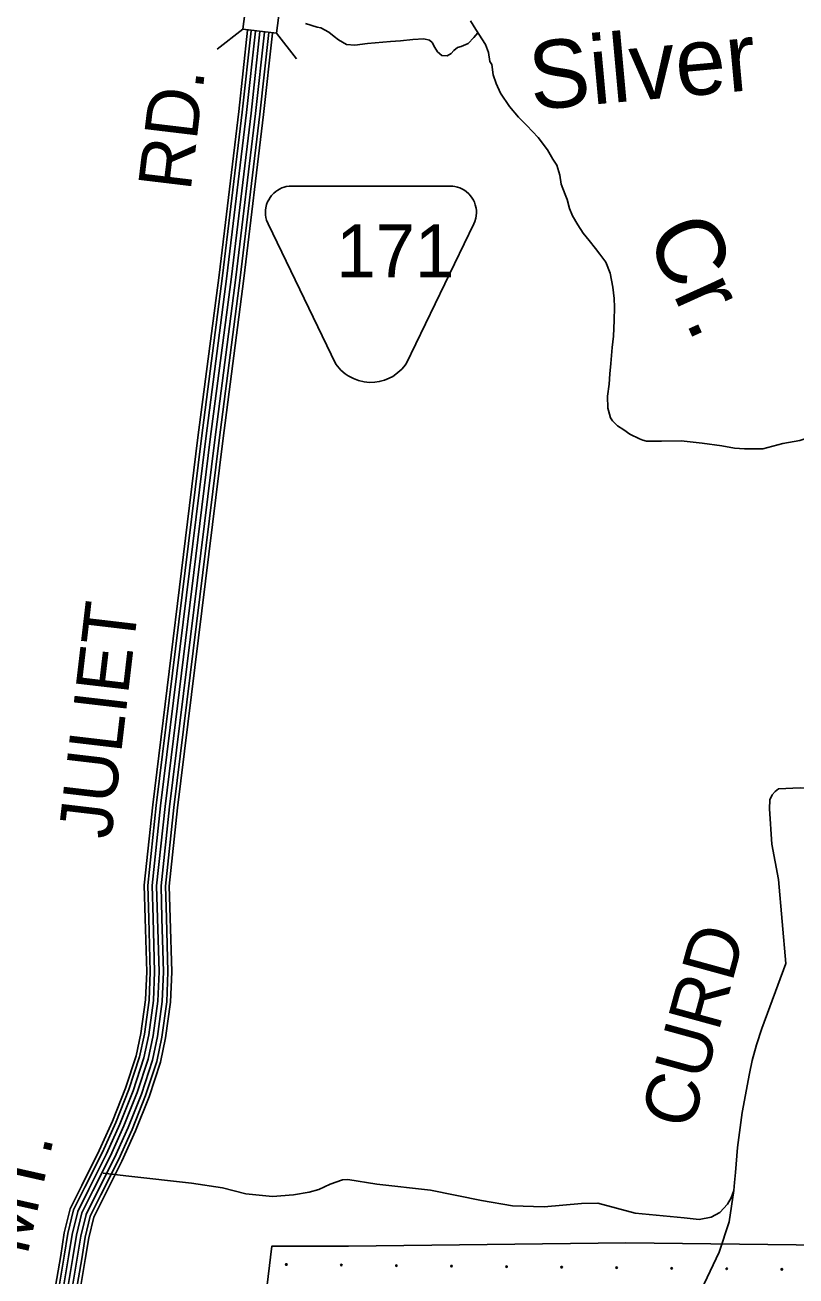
# Model space of a CAD drawing. Extents: x 1788175 to 1969470, y 584502 to 738744.
# Drawn here: x 1815246 to 1820631, y 681239 to 689981 of the extents above; entities that cross this region are included whole.
import ezdxf

# ---------------------------------------------------------------- set-up
doc = ezdxf.new("R2010")
doc.units = 0
for name, color, linetype in [('DESIGN - DRAINAGE - Bridges and Cross Drains Size Text', 7, 'Continuous'), ('DESIGN - EROSION CONTROL - Devices', 7, 'Continuous'), ('DESIGN - ROW - Easement Linework and Patterning', 7, 'Continuous'), ('DESIGN - ROW - Right-of-Way and Easement Labels', 7, 'Continuous'), ('DESIGN - SCRATCH - User 1', 7, 'Continuous'), ('DESIGN - TRANSPORTATION - Text', 7, 'Continuous'), ('SURVEY - CONTOURS - Intermediate with optional Text', 7, 'Continuous'), ('SURVEY - CONTROL with Text', 7, 'Continuous'), ('SURVEY - DRAINAGE - Area Shapes', 7, 'Continuous'), ('SURVEY - DRAINAGE - Storm Sewer', 7, 'Continuous')]:
    doc.layers.add(name, color=color, linetype=linetype)

msp = doc.modelspace()

# ---------------------------------------------------------------- linework, layer by layer
at = {"layer": 'DESIGN - EROSION CONTROL - Devices'}
for centre in [(1817071.7, 681319.3), (1817456.2, 681315.5), (1817840.8, 681311.8), (1818225.3, 681308.1), (1818609.9, 681304.3), (1818994.4, 681300.6), (1819379, 681296.9), (1819763.5, 681293.1), (1820148.1, 681289.4), (1820532.6, 681285.7)]:
    msp.add_circle(centre, 5.28, dxfattribs=at)
at = {"layer": 'DESIGN - ROW - Easement Linework and Patterning'}
for points in [[(1817418.4, 687609.8), (1816943.9, 688590.3), (1816933.4, 688617.3), (1816928.9, 688635.3), (1816926.3, 688653.2), (1816925.5, 688668.8), (1816926.2, 688686.6), (1816928.3, 688703.1), (1816934, 688726.3), (1816940.6, 688743.9), (1816948.5, 688760), (1816958.5, 688776.2), (1816968.8, 688789.7), (1816984.2, 688805.9), (1816998.5, 688817.9), (1817011.7, 688827.1), (1817024.4, 688834.4), (1817040.9, 688842.1), (1817056.6, 688847.6), (1817069.3, 688851), (1817091, 688854.6), (1817110.3, 688855.6)], [(1818381, 688590.3), (1818387.1, 688608), (1818395.1, 688631.1), (1818398, 688647.8), (1818399.4, 688668.2), (1818399, 688683.4), (1818396.9, 688701.4), (1818391.7, 688723.8), (1818385.1, 688742), (1818378.3, 688756.5), (1818369.7, 688771.4), (1818358, 688787.4), (1818345.4, 688801.3), (1818326.7, 688817.7), (1818311.8, 688827.9), (1818297.9, 688835.7), (1818283.6, 688842.2), (1818267.4, 688847.9), (1818247.6, 688852.6), (1818233.7, 688854.6), (1818214.6, 688855.6), (1817110.3, 688855.6)], [(1818381, 688590.3), (1817907.9, 687612.7), (1817892.7, 687592.4), (1817878.3, 687576.1), (1817865, 687563), (1817836.9, 687539.9), (1817814.8, 687525.3), (1817790.8, 687512.5), (1817758, 687499.1), (1817720.3, 687489), (1817688.6, 687484.5), (1817653.6, 687483.4), (1817616.2, 687486.8), (1817575.8, 687496.1), (1817540, 687509.5), (1817504.4, 687528.5), (1817482.4, 687543.5), (1817453, 687569), (1817418.4, 687609.8)]]:
    msp.add_lwpolyline(points, dxfattribs=at)
at = {"layer": 'DESIGN - SCRATCH - User 1'}
msp.add_line((1819442.8, 681470.8), (1821367.4, 681447.5), dxfattribs=at)
msp.add_lwpolyline([(1816364.3, 676041.4), (1816697.1, 679318.3), (1816771.7, 679848.1), (1816876.6, 680677), (1816969.9, 681447.5), (1817506.5, 681447.5), (1819442.8, 681470.8)], dxfattribs=at)
at = {"layer": 'DESIGN - TRANSPORTATION - Text'}
for points in [[(1817205, 689990.5), (1817286.9, 689964.4), (1817312.9, 689960.4), (1817368.8, 689930.4), (1817404.7, 689900.4), (1817436.7, 689876.4), (1817492.6, 689844.3), (1817550.6, 689840.3), (1817638.6, 689852.1), (1817798.5, 689865.9), (1817868.5, 689869.9), (1817954.5, 689879.7), (1818032.5, 689883.6), (1818072.4, 689875.6), (1818090.4, 689857.6), (1818108.3, 689823.6), (1818126.3, 689793.6), (1818158.2, 689767.6), (1818194.2, 689765.6), (1818222.2, 689781.5), (1818242.2, 689801.5), (1818268.3, 689823.4), (1818292.3, 689831.4), (1818342.3, 689851.3), (1818380.3, 689893.2), (1818409, 689926.8)], [(1818358.5, 690009.1), (1818394.4, 689949.2), (1818462.2, 689845.2), (1818484.1, 689789.2), (1818494, 689725.3), (1818506, 689705.3), (1818515.8, 689631.3), (1818537.7, 689571.4), (1818567.6, 689505.4), (1818631.4, 689411.4), (1818693.3, 689337.4), (1818751.2, 689277.4), (1818831, 689195.4), (1818894.8, 689107.4), (1818932.7, 689043.4), (1818960.6, 689001.4), (1818982.5, 688931.5), (1818992.4, 688869.5)], [(1818992.4, 688869.5), (1819020.3, 688795.5), (1819032.2, 688761.6), (1819050.1, 688697.6), (1819070, 688647.6), (1819107.9, 688583.6), (1819145.8, 688525.7), (1819187.7, 688475.7), (1819231.6, 688419.7), (1819261.5, 688379.7), (1819303.4, 688323.7), (1819333.2, 688247.7), (1819353.1, 688147.8), (1819360.9, 688069.8), (1819364.8, 688009.9), (1819360.7, 687916), (1819356.5, 687806.1), (1819348.4, 687726.2), (1819338.2, 687614.3), (1819332.1, 687542.4), (1819326, 687470.5), (1819315.9, 687386.6), (1819317.7, 687302.6), (1819321.7, 687286.6), (1819335.6, 687236.7), (1819349.6, 687214.7), (1819385.5, 687180.7), (1819429.4, 687150.7), (1819471.4, 687120.6), (1819537.3, 687088.6), (1819562.5, 687080.5)], [(1819562.5, 687080.5), (1819587.2, 687072.5), (1819691.2, 687072.4), (1819829.1, 687074.3), (1819977, 687058.1), (1820112.9, 687040), (1820202.9, 687023.9), (1820272.8, 687019.8), (1820398.8, 687019.6), (1820538.8, 687057.4), (1820658.8, 687077.3), (1820808.8, 687125.1), (1820942.8, 687148.9), (1821008.8, 687162.8)]]:
    msp.add_lwpolyline(points, dxfattribs=at)
at = {"layer": 'SURVEY - CONTOURS - Intermediate with optional Text'}
msp.add_lwpolyline([(1819814.4, 680913), (1819837.3, 680943.8), (1819968.7, 681141.1), (1820094.2, 681406.3), (1820165.1, 681617.9), (1820196.9, 681835.8)], dxfattribs=at)
at = {"layer": 'SURVEY - CONTROL with Text'}
for points in [[(1815299.7, 679944.6), (1815394.8, 680672.1), (1815450.3, 681115), (1815495.3, 681381.9), (1815520.3, 681540.9), (1815562, 681709.5), (1815642.7, 681871.8), (1815764.7, 682115.7), (1815857.8, 682321.8), (1815948.7, 682550.9), (1816023.1, 682777.4), (1816056, 682933.4), (1816087.8, 683167.9), (1816096.1, 683364.6), (1816085.3, 683737), (1816078.4, 683969.1), (1816138.3, 684530.4), (1816454.2, 687097.6), (1816601.6, 688231.7), (1816739, 689375.1), (1816801.3, 689945)], [(1815325.8, 679953.8), (1815419.3, 680669), (1815474.8, 681111.4), (1815519.7, 681378), (1815544.6, 681536), (1815585.3, 681701), (1815664.8, 681860.7), (1815787, 682105.1), (1815880.5, 682312.1), (1815972, 682542.5), (1816047, 682771), (1816080.4, 682929.2), (1816112.4, 683165.7), (1816120.8, 683364.4), (1816110, 683737.8), (1816103.1, 683968.1), (1816162.8, 684527.6), (1816478.7, 687094.5), (1816626.1, 688228.7), (1816763.5, 689372.3), (1816825.6, 689940.2)], [(1815357.6, 679957.8), (1815450, 680665), (1815505.4, 681106.9), (1815550.3, 681373), (1815575, 681529.9), (1815614.6, 681690.2), (1815692.6, 681846.9), (1815815, 682091.8), (1815909.1, 682300), (1816001.1, 682532), (1816077, 682763), (1816110.9, 682923.9), (1816143.3, 683163), (1816151.8, 683364.2), (1816141, 683738.7), (1816134.2, 683967), (1816193.6, 684524.1), (1816509.5, 687090.6), (1816656.9, 688224.8), (1816794.3, 689368.8), (1816856.5, 689937.8)], [(1815388.7, 679956.1), (1815480.8, 680661.1), (1815536.1, 681102.4), (1815580.9, 681368), (1815605.4, 681523.7), (1815643.9, 681679.5), (1815720.3, 681833.1), (1815843, 682078.4), (1815937.6, 682287.9), (1816030.3, 682521.4), (1816107, 682754.9), (1816141.5, 682918.6), (1816174.2, 683160.3), (1816182.9, 683364), (1816172, 683739.6), (1816165.2, 683965.8), (1816224.4, 684520.5), (1816540.2, 687086.7), (1816687.7, 688221), (1816825.1, 689365.2), (1816887.3, 689934.1)], [(1815418.8, 679947.7), (1815511.5, 680657.2), (1815566.8, 681097.9), (1815611.5, 681363), (1815635.8, 681517.6), (1815673.1, 681668.7), (1815748, 681819.2), (1815871, 682065.1), (1815966.2, 682275.8), (1816059.5, 682510.8), (1816137, 682746.9), (1816172.1, 682913.3), (1816205.1, 683157.5), (1816213.9, 683363.8), (1816203, 683740.5), (1816196.3, 683964.6), (1816255.2, 684517), (1816571, 687082.8), (1816718.4, 688217.1), (1816855.9, 689361.7), (1816918.1, 689930.3)], [(1815448.3, 679933.6), (1815542.3, 680653.2), (1815597.5, 681093.4), (1815642.1, 681358), (1815666.2, 681511.5), (1815702.4, 681658), (1815775.8, 681805.4), (1815899, 682051.8), (1815994.7, 682263.7), (1816088.6, 682500.3), (1816167, 682738.8), (1816202.6, 682908.1), (1816236.1, 683154.8), (1816244.9, 683363.6), (1816234, 683741.4), (1816227.3, 683963.4), (1816286, 684513.5), (1816601.7, 687078.9), (1816749.2, 688213.3), (1816886.7, 689358.2), (1816949, 689928.1)], [(1815472, 679916.9), (1815567.8, 680650), (1815622.9, 681089.7), (1815667.5, 681353.9), (1815691.5, 681506.4), (1815726.7, 681649), (1815798.8, 681793.9), (1815922.2, 682040.8), (1816018.4, 682253.7), (1816112.8, 682491.5), (1816191.8, 682732.1), (1816228, 682903.7), (1816261.7, 683152.5), (1816270.6, 683363.4), (1816259.7, 683742.2), (1816253.1, 683962.4), (1816311.6, 684510.5), (1816627.2, 687075.7), (1816774.7, 688210.1), (1816912.3, 689355.2), (1816974.5, 689924.7)]]:
    msp.add_lwpolyline(points, dxfattribs=at)
at = {"layer": 'SURVEY - DRAINAGE - Area Shapes'}
for points in [[(1820832.1, 684611.8), (1820762.7, 684626.6), (1820759.2, 684631.8), (1820738.1, 684638.1), (1820721.3, 684646.6), (1820661.4, 684651.3), (1820509.3, 684642.3), (1820485.4, 684625.5), (1820464.3, 684600.2), (1820449.6, 684566.4), (1820447.6, 684503.4), (1820463, 684256.5), (1820509.3, 684009.5), (1820559.5, 683423.7)], [(1820559.5, 683423.7), (1820392.8, 682968.3), (1820354.6, 682854.5), (1820324.4, 682744.7), (1820306.3, 682654.8), (1820255.8, 682381.1), (1820223.4, 682137.4), (1820209.1, 681961.6), (1820203, 681891.7), (1820196.9, 681835.8), (1820178.8, 681785.8), (1820152.8, 681739.9), (1820100.7, 681682), (1820038.7, 681650.1), (1819954.7, 681634.3), (1819850.8, 681646.4), (1819507.1, 681678.7), (1819247.3, 681747), (1819133.4, 681745.1), (1818871.5, 681723.4), (1818651.7, 681729.7), (1818435.9, 681765.9), (1818078.2, 681838.3), (1817704.5, 681880.6), (1817500.7, 681912.8), (1817462.7, 681910.9), (1817378.7, 681881), (1817298.7, 681843.2), (1817230.7, 681825.3), (1817120.8, 681805.4), (1816974.8, 681793.6), (1816789.6, 681814.1), (1816625.2, 681855.9), (1816409.4, 681888.2), (1815971.7, 681936.6), (1815791.2, 681958.4)]]:
    msp.add_lwpolyline(points, dxfattribs=at)
at = {"layer": 'SURVEY - DRAINAGE - Storm Sewer'}
for p, q in [((1816767.9, 689951.8), (1816589, 689812)), ((1817003.8, 689922.8), (1817143.5, 689743.9))]:
    msp.add_line(p, q, dxfattribs=at)
msp.add_lwpolyline([(1816796.9, 690187.7), (1816767.9, 689951.8), (1817003.8, 689922.8), (1817032.7, 690158.7)], close=True, dxfattribs=at)

# ---------------------------------------------------------------- texts
at = {"layer": 'DESIGN - DRAINAGE - Bridges and Cross Drains Size Text'}
for s, rotation, p in [('Silver', 5.19481, (1818787.2, 689385.7)), ('Cr.', 294.37084, (1819580.9, 688521.5))]:
    msp.add_text(s, height=475, rotation=rotation, dxfattribs=at).set_placement(p)
at = {"layer": 'DESIGN - ROW - Easement Linework and Patterning'}
msp.add_text('171', height=369.6, dxfattribs=at).set_placement((1817420.5, 688217.1))
at = {"layer": 'DESIGN - ROW - Right-of-Way and Easement Labels'}
for s, rotation, p in [('RD.', 83.1491, (1816402.3, 688814.2)), (' JULIET', 83.29762, (1815830.6, 684148.5)), ('CURD', 74.64012, (1819900.5, 682251)), ('MT. ', 77.28501, (1815261.6, 681376))]:
    msp.add_text(s, height=370, rotation=rotation, dxfattribs=at).set_placement(p)

doc.saveas('drawing.dxf')
